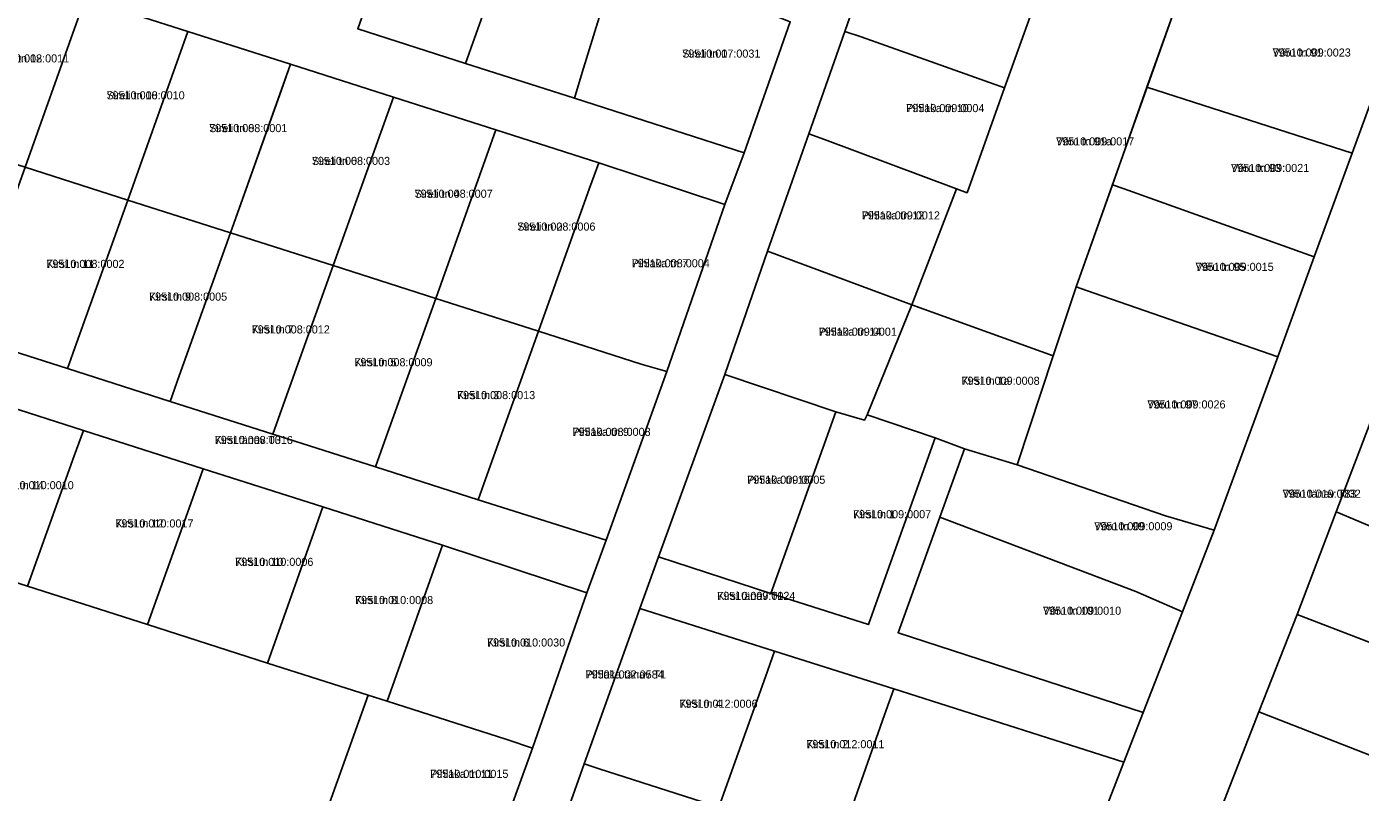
# Model space of a CAD drawing. Extents: x 643847 to 663718, y 6468443 to 6482775.
# Drawn here: x 658986.5 to 659233.9, y 6471257.8 to 6471399.9 of the extents above; entities that cross this region are included whole.
import ezdxf

# ---------------------------------------------------------------- set-up
doc = ezdxf.new("R2010")
doc.units = 0
for name, color, linetype in [('L_AADRESS', 7, 'Continuous'), ('PIIR', 7, 'Continuous'), ('TUNNUS', 7, 'Continuous')]:
    doc.layers.add(name, color=color, linetype=linetype)

msp = doc.modelspace()

# ---------------------------------------------------------------- linework, layer by layer
at = {"layer": 'PIIR'}
for points in [[(659172.33, 6471217.52), (659190.04, 6471263.38), (659193.61, 6471272.61), (659200.97, 6471291.29), (659206.83, 6471306.43), (659218.63, 6471338.59), (659225.4, 6471357.14), (659232.41, 6471376.4), (659241.61, 6471401.62), (659208.77, 6471412.28), (659204.28, 6471409.83), (659201.66, 6471420.56), (659209.98, 6471416.96), (659243.06, 6471406.15), (659246.34, 6471438.6), (659251.31, 6471438.1), (659256.98, 6471465.36), (659249.04, 6471466.01), (659251.84, 6471493.3), (659254.42, 6471525.93)], [(659293.84, 6471523.06), (659293.08, 6471520.32), (659284.08, 6471483.09), (659285.16, 6471470.96), (659271.69, 6471434.18), (659266.8, 6471412.32), (659260.94, 6471394.17), (659252.39, 6471370.52), (659250.13, 6471364.86), (659246.98, 6471356.23), (659244.47, 6471349.41), (659243.69, 6471346.68), (659236.54, 6471328.46), (659229.47, 6471309.85), (659222.21, 6471290.78), (659215.12, 6471272.69), (659207.74, 6471253.86)], [(659058.88, 6471430.57), (659047.91, 6471399.49), (659067.89, 6471393.06), (659088.11, 6471386.6), (659119.57, 6471376.44), (659116.01, 6471366.89), (659092.61, 6471374.64), (659073.55, 6471380.72), (659054.5, 6471386.81), (659035.44, 6471392.9), (659016.39, 6471398.99), (658997.34, 6471405.1)], [(659144.88, 6471417.97), (659138.29, 6471399.01), (659131.63, 6471379.98), (659123.91, 6471358.22), (659116.01, 6471335.35), (659103.7, 6471301.5), (659100.27, 6471291.91), (659089.93, 6471263.07), (659082.3, 6471241.6)], [(659072.78, 6471245.1), (659080.35, 6471265.98), (659090.43, 6471294.81), (659094.02, 6471304.55), (659105.23, 6471335.86), (659116.01, 6471366.89), (659119.57, 6471376.44), (659128.14, 6471400.77)]]:
    msp.add_lwpolyline(points, dxfattribs=at)
for points in [[(659047.91, 6471399.49), (659058.88, 6471430.57), (659078.99, 6471424.13), (659069.57, 6471397.77), (659067.89, 6471393.06)], [(659204.28, 6471409.83), (659201.16, 6471407.88), (659181.21, 6471351.6), (659176.95, 6471338.79), (659150.69, 6471348.24), (659159.03, 6471369.76), (659160.96, 6471369.05), (659167.92, 6471388.53), (659174.64, 6471407.33), (659181.28, 6471425.92), (659181.49, 6471427.81), (659201.66, 6471420.56)], [(659067.89, 6471393.06), (659069.57, 6471397.77), (659078.99, 6471424.13), (659097.94, 6471418.07), (659095.84, 6471411.84), (659089.57, 6471391.37), (659088.11, 6471386.6)], [(659144.88, 6471417.97), (659148.04, 6471416.83), (659174.64, 6471407.33), (659167.92, 6471388.53), (659141.32, 6471398.03), (659138.29, 6471399.01)], [(658973.51, 6471412.7), (658997.34, 6471405.1), (658995.66, 6471400.39), (658986.17, 6471373.8), (658967.1, 6471379.88), (658962.33, 6471381.4)], [(659119.57, 6471376.44), (659088.11, 6471386.6), (659089.57, 6471391.37), (659095.84, 6471411.84), (659124.05, 6471402.39), (659128.14, 6471400.77)], [(659241.61, 6471401.62), (659232.41, 6471376.4), (659194.35, 6471388.67), (659201.16, 6471407.88), (659204.28, 6471409.83), (659208.77, 6471412.28)], [(659016.39, 6471398.99), (659014.71, 6471394.28), (659005.22, 6471367.71), (658986.17, 6471373.8), (658995.66, 6471400.39), (658997.34, 6471405.1)], [(659035.44, 6471392.9), (659033.76, 6471388.19), (659024.27, 6471361.63), (659005.22, 6471367.71), (659014.71, 6471394.28), (659016.39, 6471398.99)], [(659138.29, 6471399.01), (659141.32, 6471398.03), (659167.92, 6471388.53), (659160.96, 6471369.05), (659159.03, 6471369.76), (659134.51, 6471378.95), (659131.63, 6471379.98)], [(659054.5, 6471386.81), (659043.33, 6471355.54), (659024.27, 6471361.63), (659035.44, 6471392.9)], [(659232.41, 6471376.4), (659225.4, 6471357.14), (659189.9, 6471369.83), (659187.92, 6471370.53), (659194.35, 6471388.67)], [(659073.55, 6471380.72), (659071.87, 6471376.01), (659062.38, 6471349.44), (659043.33, 6471355.54), (659054.5, 6471386.81)], [(659092.61, 6471374.64), (659090.92, 6471369.93), (659081.43, 6471343.35), (659062.38, 6471349.44), (659071.87, 6471376.01), (659073.55, 6471380.72)], [(659131.63, 6471379.98), (659134.51, 6471378.95), (659159.03, 6471369.76), (659150.69, 6471348.24), (659123.91, 6471358.22)], [(658975, 6471342.51), (658976.68, 6471347.22), (658986.17, 6471373.8), (659005.22, 6471367.71), (658995.73, 6471341.14), (658994.05, 6471336.43)], [(659105.23, 6471335.86), (659100.49, 6471337.26), (659081.43, 6471343.35), (659090.92, 6471369.93), (659092.61, 6471374.64), (659116.01, 6471366.89)], [(659218.63, 6471338.59), (659183.1, 6471350.92), (659181.21, 6471351.6), (659187.92, 6471370.53), (659189.9, 6471369.83), (659225.4, 6471357.14)], [(659005.22, 6471367.71), (659024.27, 6471361.63), (659014.78, 6471335.06), (659013.1, 6471330.34), (658994.05, 6471336.43), (658995.73, 6471341.14)], [(659013.1, 6471330.34), (659014.78, 6471335.06), (659024.27, 6471361.63), (659043.33, 6471355.54), (659033.83, 6471328.96), (659032.15, 6471324.25)], [(659123.91, 6471358.22), (659150.69, 6471348.24), (659142.43, 6471327.84), (659141.91, 6471326.82), (659136.62, 6471328.38), (659116.01, 6471335.35)], [(659032.15, 6471324.25), (659033.83, 6471328.96), (659043.33, 6471355.54), (659062.38, 6471349.44), (659052.89, 6471322.87), (659051.2, 6471318.16)], [(659218.63, 6471338.59), (659206.83, 6471306.43), (659197.77, 6471309.12), (659170.26, 6471318.58), (659176.95, 6471338.79), (659181.21, 6471351.6), (659183.1, 6471350.92)], [(659094.02, 6471304.55), (659090.43, 6471294.81), (659063.64, 6471303.63), (659041.42, 6471310.73), (659019.2, 6471317.83), (658996.98, 6471324.94), (658974.77, 6471332.05), (658947.78, 6471340.68), (658951.15, 6471350.04), (658975, 6471342.51), (658994.05, 6471336.43), (659013.1, 6471330.34), (659032.15, 6471324.25), (659051.2, 6471318.16), (659070.26, 6471312.06)], [(659051.2, 6471318.16), (659052.89, 6471322.87), (659062.38, 6471349.44), (659081.43, 6471343.35), (659071.94, 6471316.77), (659070.26, 6471312.06)], [(659160.51, 6471321.53), (659155.03, 6471323.57), (659142.43, 6471327.84), (659150.69, 6471348.24), (659176.95, 6471338.79), (659170.26, 6471318.58)], [(659094.02, 6471304.55), (659070.26, 6471312.06), (659071.94, 6471316.77), (659081.43, 6471343.35), (659100.49, 6471337.26), (659105.23, 6471335.86)], [(659116.01, 6471335.35), (659136.62, 6471328.38), (659124.56, 6471294.7), (659103.7, 6471301.5)], [(658973.08, 6471327.33), (658974.77, 6471332.05), (658996.98, 6471324.94), (658995.3, 6471320.22), (658986.62, 6471296.03), (658964.4, 6471303.08)], [(659124.56, 6471294.7), (659136.62, 6471328.38), (659141.91, 6471326.82), (659142.43, 6471327.84), (659155.03, 6471323.57), (659144.34, 6471293.62), (659142.66, 6471288.91)], [(659236.54, 6471328.46), (659272.93, 6471313.72), (659272.07, 6471311.51), (659269.79, 6471305.72), (659267.54, 6471300.02), (659265.46, 6471294.7), (659229.47, 6471309.85)], [(658995.3, 6471320.22), (658996.98, 6471324.94), (659019.2, 6471317.83), (659017.52, 6471313.12), (659008.9, 6471288.89), (658986.62, 6471296.03)], [(659193.61, 6471272.61), (659190.04, 6471263.38), (659147.36, 6471276.95), (659125.25, 6471283.97), (659100.27, 6471291.91), (659103.7, 6471301.5), (659124.56, 6471294.7), (659142.66, 6471288.91), (659144.34, 6471293.62), (659155.03, 6471323.57), (659160.51, 6471321.53), (659155.91, 6471308.84), (659148.15, 6471287.4)], [(659200.97, 6471291.29), (659192.3, 6471295.05), (659155.91, 6471308.84), (659160.51, 6471321.53), (659170.26, 6471318.58), (659197.77, 6471309.12), (659206.83, 6471306.43)], [(658911.5, 6471289.28), (658921.71, 6471317.51), (658923.39, 6471316.97), (658928.1, 6471315.27), (658937.55, 6471311.92), (658942.23, 6471310.21), (658964.4, 6471303.08), (658986.62, 6471296.03), (659008.9, 6471288.89), (659031.13, 6471281.77), (659049.85, 6471275.8), (659042.37, 6471254.9), (659034.97, 6471234.19), (659033.06, 6471234.76), (659026.61, 6471216.62), (659019.78, 6471197.55), (659012.93, 6471178.37), (658889.96, 6471221.72), (658898.3, 6471248.52), (658908.55, 6471280.75)], [(659041.42, 6471310.73), (659039.74, 6471306.02), (659031.13, 6471281.77), (659008.9, 6471288.89), (659017.52, 6471313.12), (659019.2, 6471317.83)], [(659063.64, 6471303.63), (659061.96, 6471298.92), (659053.33, 6471274.67), (659049.85, 6471275.8), (659031.13, 6471281.77), (659039.74, 6471306.02), (659041.42, 6471310.73)], [(659148.15, 6471287.4), (659155.91, 6471308.84), (659192.3, 6471295.05), (659200.97, 6471291.29), (659193.61, 6471272.61)], [(659229.47, 6471309.85), (659265.46, 6471294.7), (659265.3, 6471294.31), (659258.42, 6471276.83), (659222.21, 6471290.78)], [(659063.64, 6471303.63), (659090.43, 6471294.81), (659080.35, 6471265.98), (659075.53, 6471267.57), (659053.33, 6471274.67), (659061.96, 6471298.92)], [(659125.25, 6471283.97), (659123.54, 6471279.2), (659114.9, 6471254.99), (659092.68, 6471262.1), (659089.93, 6471263.07), (659100.27, 6471291.91)], [(659222.21, 6471290.78), (659258.42, 6471276.83), (659256.17, 6471271.12), (659253.97, 6471265.52), (659251.72, 6471259.81), (659251.25, 6471258.6), (659215.12, 6471272.69)], [(659147.36, 6471276.95), (659145.66, 6471272.14), (659137.12, 6471247.9), (659116.97, 6471254.33), (659114.9, 6471254.99), (659123.54, 6471279.2), (659125.25, 6471283.97)], [(659172.33, 6471217.52), (659162.78, 6471220.55), (659130.98, 6471230.64), (659137.12, 6471247.9), (659145.66, 6471272.14), (659147.36, 6471276.95), (659190.04, 6471263.38)], [(659072.78, 6471245.1), (659068.07, 6471246.67), (659042.37, 6471254.9), (659049.85, 6471275.8), (659053.33, 6471274.67), (659075.53, 6471267.57), (659080.35, 6471265.98)], [(659215.12, 6471272.69), (659251.25, 6471258.6), (659249.48, 6471254.11), (659247.24, 6471248.41), (659245, 6471242.71), (659243.74, 6471239.52), (659207.74, 6471253.86)], [(659089.93, 6471263.07), (659092.68, 6471262.1), (659114.9, 6471254.99), (659116.97, 6471254.33), (659109.27, 6471232.75), (659082.3, 6471241.6)]]:
    msp.add_lwpolyline(points, close=True, dxfattribs=at)

# ---------------------------------------------------------------- texts
at = {"layer": 'L_AADRESS'}
for s, p in [('Sireli tn 1', (659108.11, 6471394.14)), ('Võru tn 91', (659217.66, 6471394.34)), ('Sireli tn 12', (658979.84, 6471393.25)), ('Sireli tn 10', (659001.28, 6471386.4)), ('Pihlaka tn 10', (659149.68, 6471384.03)), ('Sireli tn 8', (659020.33, 6471380.31)), ('Võru tn 91a', (659177.48, 6471377.85)), ('Sireli tn 6', (659039.39, 6471374.22)), ('Võru tn 93', (659209.95, 6471372.91)), ('Sireli tn 4', (659058.44, 6471368.13)), ('Pihlaka tn 12', (659141.42, 6471364.11)), ('Sireli tn 2', (659077.5, 6471362.03)), ('Kirsi tn 11', (658990.11, 6471355.11)), ('Pihlaka tn 7', (659098.72, 6471355.22)), ('Võru tn 95', (659203.36, 6471354.56)), ('Kirsi tn 9', (659009.16, 6471349.03)), ('Kirsi tn 7', (659028.21, 6471342.94)), ('Pihlaka tn 14', (659133.43, 6471342.52)), ('Kirsi tn 5', (659047.27, 6471336.85)), ('Kirsi tn 1a', (659159.93, 6471333.41)), ('Kirsi tn 3', (659066.32, 6471330.75)), ('Võru tn 97', (659194.42, 6471329.02)), ('Kirsi tänav T3', (659021.35, 6471322.42)), ('Pihlaka tn 9', (659087.74, 6471323.93)), ('Pihlaka tn 16', (659120.16, 6471315.04)), ('Kirsi tn 14', (658980.69, 6471314.03)), ('Võru tänav T83', (659219.51, 6471312.45)), ('Kirsi tn 1', (659139.8, 6471308.64)), ('Kirsi tn 12', (659002.91, 6471306.93)), ('Võru tn 99', (659184.57, 6471306.41)), ('Kirsi tn 10', (659025.16, 6471299.8)), ('Kirsi tn 8', (659047.39, 6471292.71)), ('Kirsi tänav T1', (659114.61, 6471293.48)), ('Võru tn 101', (659175.05, 6471290.73)), ('Kirsi tn 6', (659071.88, 6471284.83)), ('Pihlaka tänav T1', (659090.17, 6471278.9)), ('Kirsi tn 4', (659107.59, 6471273.46)), ('Kirsi tn 2', (659131.13, 6471265.96)), ('Pihlaka tn 11', (659061.35, 6471260.45))]:
    msp.add_text(s, height=1.5, dxfattribs=at).set_placement(p)
at = {"layer": 'TUNNUS'}
for s, p in [('79510:007:0031', (659108.11, 6471394.14)), ('79510:009:0023', (659217.66, 6471394.34)), ('79510:008:0011', (658979.84, 6471393.25)), ('79510:008:0010', (659001.28, 6471386.4)), ('79510:009:0004', (659149.68, 6471384.03)), ('79510:008:0001', (659020.33, 6471380.31)), ('79510:009:0017', (659177.48, 6471377.85)), ('79510:008:0003', (659039.39, 6471374.22)), ('79510:009:0021', (659209.95, 6471372.91)), ('79510:008:0007', (659058.44, 6471368.13)), ('79510:008:0006', (659077.5, 6471362.03)), ('79510:009:0012', (659141.42, 6471364.11)), ('79510:008:0002', (658990.11, 6471355.11)), ('79510:008:0004', (659098.72, 6471355.22)), ('79510:009:0015', (659203.36, 6471354.56)), ('79510:008:0005', (659009.16, 6471349.03)), ('79510:008:0012', (659028.21, 6471342.94)), ('79510:009:0001', (659133.43, 6471342.52)), ('79510:008:0009', (659047.27, 6471336.85)), ('79510:009:0008', (659159.93, 6471333.41)), ('79510:008:0013', (659066.32, 6471330.75)), ('79510:009:0026', (659194.42, 6471329.02)), ('79510:008:0016', (659021.35, 6471322.42)), ('79510:008:0008', (659087.74, 6471323.93)), ('79510:009:0005', (659120.16, 6471315.04)), ('79510:010:0010', (658980.69, 6471314.03)), ('79510:019:0032', (659219.51, 6471312.45)), ('79510:009:0007', (659139.8, 6471308.64)), ('79510:010:0017', (659002.91, 6471306.93)), ('79510:009:0009', (659184.57, 6471306.41)), ('79510:010:0006', (659025.16, 6471299.8)), ('79510:010:0008', (659047.39, 6471292.71)), ('79510:009:0024', (659114.61, 6471293.48)), ('79510:009:0010', (659175.05, 6471290.73)), ('79510:010:0030', (659071.88, 6471284.83)), ('79501:002:0584', (659090.17, 6471278.9)), ('79510:012:0006', (659107.59, 6471273.46)), ('79510:012:0011', (659131.13, 6471265.96)), ('79510:010:0015', (659061.35, 6471260.45))]:
    msp.add_text(s, height=1.5, dxfattribs=at).set_placement(p)

doc.saveas('drawing.dxf')
